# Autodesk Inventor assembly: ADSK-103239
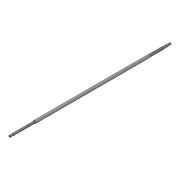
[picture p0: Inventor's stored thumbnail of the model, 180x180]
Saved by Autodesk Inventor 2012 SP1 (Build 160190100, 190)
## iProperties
Shininess: 0.0
Created: 2000-11
Part Number: ADSK-103239
Document SubType Name: Assembly
Stock Number: ADSK-103239
Density: 0.0
Volumn: 0.0
Area: 0.0
PropertySet Name: Model Information
Control State: 0
Master: False
Checked Out: False
Author: gao
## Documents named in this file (4)
- D:\AOTC\Autodesk Inventor 2012 Essential for New Users\Autodesk Inventor 2012 Essentials - Project Files\Learning\Workspace\Sub-Assemblies\ADSK-103239.iam
- D:\AOTC\Autodesk Inventor 2012 Essential for New Users\Autodesk Inventor 2012 Essentials - Project Files\Learning\Workspace\Parts\ADSK-104048.ipt
- D:\AOTC\Autodesk Inventor 2012 Essential for New Users\Autodesk Inventor 2012 Essentials - Project Files\Learning\Workspace\Parts\ADSK-104049.ipt
- D:\AOTC\Autodesk Inventor 2012 Essential for New Users\Autodesk Inventor 2012 Essentials - Project Files\Learning\Workspace\Parts\ADSK-104047.ipt
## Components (3 placed, 3 different names)
1. ADSK-104049:1 — Insert:1, Insert:2
2. ADSK-104047:1 — Insert:2
3. ADSK-104048:1 — Insert:1
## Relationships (2: Insert 2)
- Insert:1: ADSK-104049:1 ↔ ADSK-104048:1
- Insert:2: ADSK-104049:1 ↔ ADSK-104047:1
